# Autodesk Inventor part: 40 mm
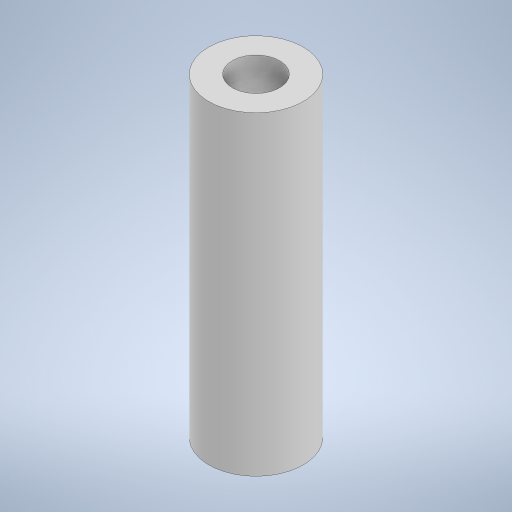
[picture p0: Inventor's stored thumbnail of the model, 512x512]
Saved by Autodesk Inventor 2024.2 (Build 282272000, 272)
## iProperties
Created: 2024-05
Part Number: 40 mm
Material: Generic
Document SubType Name: Modeling
Designer: Karsten
Density: 1 g/cm^3
Appearance: Default
Author: Karsten
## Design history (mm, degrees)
sketch "Sketch1"
  geometry: C1 r 3 at (0, 0); C2 r 6 at (0, 0); 1 further point
  constraints: 2 centre point, 2 coincident
  dimensions: "d0" = 6 diameter of C1; "d1" = 12 diameter of C2
extrude "Extrusion1" new body sketch "Sketch1" distance "d2" = 40; taper "d3" = 0 deg
body "Solid1"
